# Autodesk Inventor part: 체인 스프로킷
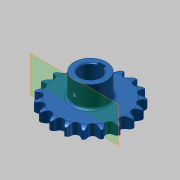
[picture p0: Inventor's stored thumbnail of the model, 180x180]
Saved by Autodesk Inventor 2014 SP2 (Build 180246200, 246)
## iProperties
Created: 2014-11
Part Number: 체인 스프로킷
Material: 강
Document SubType Name: Modeling
Designer: KYOUNG IL JANG
Density: 7.85 g/cm^3
Mass: 738.264 g
Surface Area: 236.923 cm^2
Volume: 94.0463 cm^3
Appearance: 하늘색 짙음
CustomPartVersion: 1
Company: 한국ATC센터
Author: KYOUNG IL JANG
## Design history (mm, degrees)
sketch "이론적 톱니 프로파일"
  geometry: L1 (0, 0)-(0, 45.567); L2 (0, 0)-(14.795, 43.098); L3 (0, 45.567)-(14.795, 43.098); L4 (0, 45.567)-(5.661, 50.015); L5 (5.661, 50.015)-(-5.141, 45.406); L6 (-12.428, 43.493)-(-5.573, 46.417); L7 (-5.141, 45.406)-(-5.573, 46.417); L8 (5.573, 46.417)-(5.141, 45.406); L9 (0, 0)-(8.138, 48.771); A1 r 45.567 centre (0, 0) between (0, 45.567) and (14.795, 43.098); A2 r 49.445 centre (0, 0) between (7.302, 48.903) and (-7.302, 48.903); A3 r 4.545 centre (0, 45.567) between (-3.574, 42.758) and (3.574, 42.758); A4 r 7.453 centre (12.428, 43.493) between (7.302, 48.903) and (5.573, 46.417); A5 r 7.453 centre (-12.428, 43.493) between (-5.573, 46.417) and (-7.302, 48.903); A6 r 11.745 centre (5.661, 50.015) between (-5.141, 45.406) and (-3.574, 42.758); A7 r 11.745 centre (-5.661, 50.015) between (3.574, 42.758) and (5.141, 45.406); 2 further points
  constraints: 18 end point, 15 point on circle, 7 centre point, 3 coincident, 3 point on line, 3 symmetric about line, 3 tangent, 1 equal radius, 1 midpoint, 1 parallel, 1 vertical, 1 other
  dimensions: "d0" = 91.13301 diameter of A1 (computed from da_p, da_z); "d2" = 18.9474 deg angle of L2 L1 (computed from da_z); "d3" = 4.545 radius of A3 (= 0.5 x da_Dr + da_SC); "d10" = 128.158 deg angle of L4 L1 (computed from da_z); "d11" = 15.0526 deg angle of L5 L4 (computed from da_z); "d12" = 7.2 distance of L3.start L4.end (= 0.8 x da_Dr); "d13" = 11.745 distance of L4.end L5.end (= 1.3 x da_Dr + da_SC); "d14" = 12.6 distance of A4.centre L1.end (= 1.4 x da_Dr); "d23" = 4.5 distance from line of L9.end L3 (= da_Ha)
sketch "톱니 프로파일"
  geometry: L1 (0, 0)-(0, 45.567); L2 (0, 45.567)-(4.203, 43.837); L3 (0, 45.567)-(-4.203, 43.837); A1 r 4.545 centre (0, 45.567) between (-4.203, 43.837) and (4.203, 43.837); A2 r 22.68 centre (25.176, 35.206) between (7.12, 48.93) and (4.203, 43.837); A3 r 22.68 centre (-25.176, 35.206) between (-4.203, 43.837) and (-7.12, 48.93); A4 r 49.445 centre (0, 0) between (-7.12, 48.93) and (7.12, 48.93) reference; 1 further point
  constraints: 9 point on circle, 6 end point, 3 centre point, 2 tangent, 1 coincident, 1 equal radius, 1 vertical, 1 other
  dimensions: "d44" = 135.263 deg angle of L3 L2 (= da_Alfa); "d45" = 22.68 radius of A2 (= da_Re); "d46" = 4.545 radius of A1 (= da_Ri)
sketch "단면 프로파일"
  geometry: L1 (49.445, 0)-(-49.445, 0) reference; L2 (33.265, 6.65)-(-33.265, 6.65); L3 (-33.265, 6.65)-(-33.265, -6.65); L4 (-33.265, -6.65)-(33.265, -6.65); L5 (33.265, -6.65)-(33.265, 6.65); L6 (33.265, 6.65)-(49.445, 6.65); L7 (49.445, 6.65)-(49.445, -6.65); L8 (49.445, -6.65)-(33.265, -6.65); L9 (33.265, -6.65)-(33.265, 6.65); L10 (42.183, 6.65)-(0, 6.65); L11 (0, 6.65)-(0, -6.65); L12 (0, -6.65)-(42.183, -6.65); L13 (0, 6.65)-(0, -6.65); L14 (49.445, 4.775)-(49.445, -4.775); A1 r 15 centre (42.183, -8.35) between (49.445, 4.775) and (42.183, 6.65); A2 r 15 centre (42.183, 8.35) between (42.183, -6.65) and (49.445, -4.775); 2 further points
  constraints: 26 end point, 7 midpoint, 5 perpendicular, 4 parallel, 4 point on circle, 3 point on line, 3 symmetric about line, 2 centre point, 2 horizontal, 2 tangent, 1 collinear, 1 other
  dimensions: "d30" = 13.3 distance between parallel lines of L8 L6 (= da_Bf); "d31" = 66.53007 distance between parallel lines of L3 L5 (= da_Ds); "d32" = 13.3 distance between parallel lines of L4 L2 (= da_Bs); "d33" = 1.875 distance from line of L14.start L6 (= da_Ba); "d34" = 15 radius of A1 (= da_Rx); "d43" = 6.65 distance between parallel lines of L4 L1 (computed from da_k, da_pt, da_Bs)
revolve "슈라우드" stored, may be unused: angle "d36" = 90 deg
revolve "스트랜드" stored, may be unused: angle "d37" = 90 deg
extrude "이론적 톱니" cut sketch "이론적 톱니 프로파일" stored distance "d18" = 10; taper "d19" = 0 deg; dims "d49" = 0, "form_type" = 0 [user parameter]
extrude "톱니" cut sketch "톱니 프로파일" stored distance "d47" = 10; taper "d48" = 0 deg; dims "d50" = 10, "form_type" = 0 [user parameter]
node "타이밍 평면"
node "작업 평면3"
sketch "스케치5"
  geometry: C1 r 20 at (0, -45.567); 1 further point
  constraints: 1 centre point, 1 coincident
  dimensions: "d52" = 40 diameter of C1
extrude "돌출4" join sketch "스케치5" stored distance "d53" = 10; taper "d54" = 0 deg
sketch "스케치6"
  geometry: L1 (4, 11.843)-(4, 16.5); L2 (4, 16.5)-(-4, 16.5); L3 (-4, 16.5)-(-4, 11.843); A1 r 12.5 centre (0, 0) between (4, 11.843) and (-4, 11.843); 1 further point
  constraints: 6 end point, 2 parallel, 2 point on circle, 1 centre point, 1 coincident, 1 perpendicular, 1 vertical
  dimensions: "d55" = 25 diameter of A1; "d56" = 29 dimension on A1 L2 (computed from d55); "d57" = 8 distance of L1.end L2.end
extrude "돌출5" cut sketch "스케치6" stored distance "d58" = 10; taper "d59" = 0 deg
fillet "모깎기2" dims "d60" = 3
chamfer "모따기1" distance "d61" = 1; stored, may be unused: second distance "d62" = 2, angle "d63" = 45 deg
node "작업 평면4"
sketch "스케치7"
  geometry: L1 (-13.5, -13.3)-(13.5, -13.3) reference; 4 further points
  constraints: 1 vertical alignment
  dimensions: "d65" = 25 distance from line of point (0, 11.7) L1
hole "구멍1" sketch "스케치7" at (0, 11.7) diameter "d66" = 5; stored, may be unused: countersink angle "d70" = 90 deg, drill point angle "d72" = 118 deg; dims "d67" = 6, "d68" = 4, "d69" = 2, "d71" = 8
feature "스레드1" dims "d73" = 10, "d74" = 0
body "Solid1"
pattern_linear "스트랜드 패턴" dims "d40" = 24 (= da_pt)
pattern_circular "톱니 패턴" dims angle "d21" = 360 deg
other parameters: "da_p" = 15 [user parameter; used in 1 equation term], "da_Dr" = 9 [user parameter; used in 4 equation terms], "da_SC" = 0.045 [user parameter; used in 2 equation terms], "da_Ha" = 4.5 [user parameter; used in 1 equation term], "da_pt" = 24 [user parameter; used in 2 equation terms], "da_Bf" = 13.3 [user parameter; used in 1 equation term], "d28" = 0, "d29" = 0, "da_Ba" = 1.875 [user parameter; used in 1 equation term], "da_Rx" = 15 [user parameter; used in 1 equation term], "da_Ra" = 0.6 [user parameter], "da_Bs" = 13.3 [user parameter; used in 2 equation terms], "da_Ds" = 66.53007 [user parameter; used in 1 equation term], "d42" = 0, "da_Re" = 22.68 [user parameter; used in 1 equation term], "da_Ri" = 4.545 [user parameter; used in 1 equation term], "da_Alfa" = 135.263 deg [user parameter; used in 1 equation term]
